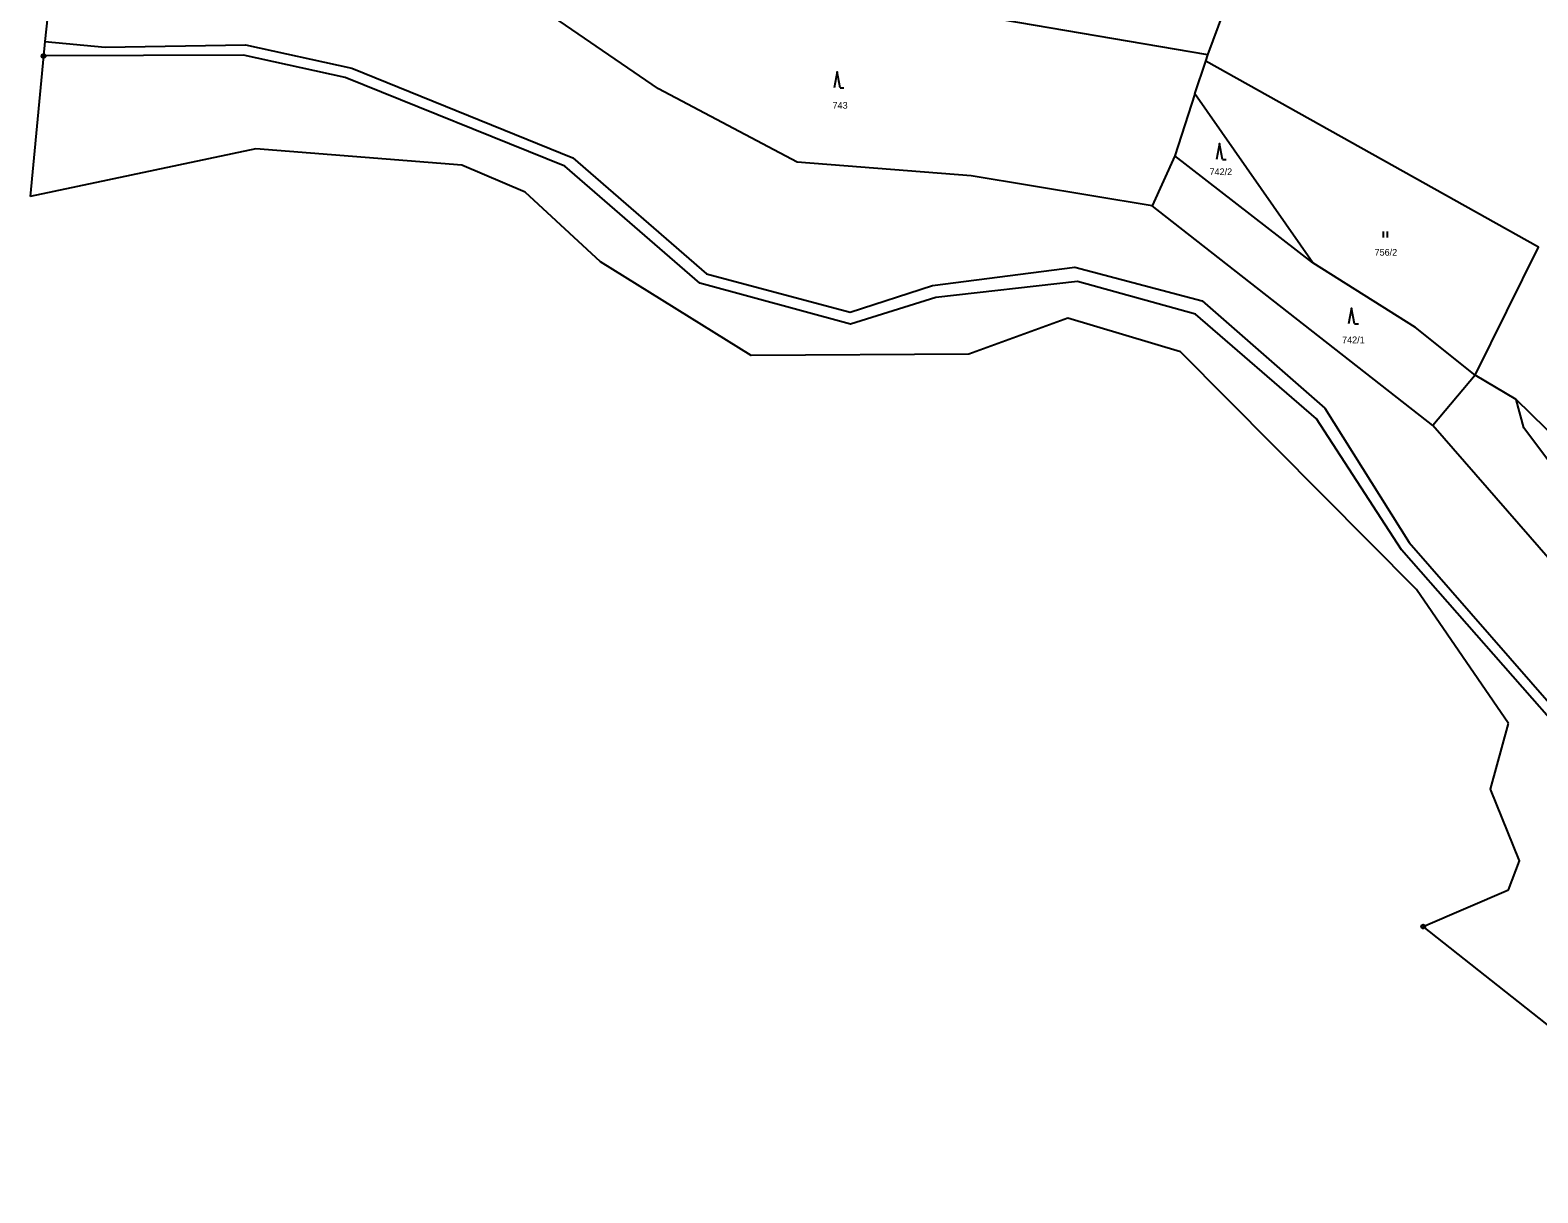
# Model space of a CAD drawing. Extents: x -687135 to -684370, y -1007309 to -1005782.
# Drawn here: x -686988.5 to -686608.2, y -1006718.8 to -1006425.4 of the extents above; entities that cross this region are included whole.
import ezdxf

# ---------------------------------------------------------------- set-up
doc = ezdxf.new("R2010")
doc.units = 0
doc.header["$LTSCALE"] = 0.68
for name, color, linetype, lineweight in [('1', 7, 'Continuous', 25), ('3', 7, 'Continuous', 25), ('8', 7, 'Continuous', 25)]:
    doc.layers.add(name, color=color, linetype=linetype, lineweight=lineweight)
doc.layers.add('2', color=7, linetype='Continuous')

msp = doc.modelspace()

# ---------------------------------------------------------------- linework, layer by layer
at = {"layer": '1'}
for p, q in [((-686984.16, -1006422.05), (-686984.76, -1006428.31)), ((-686984.76, -1006428.31), (-686985.11, -1006431.95)), ((-686985.11, -1006431.95), (-686988.5, -1006467.44)), ((-686699.82, -1006457.14), (-686705.53, -1006469.79)), ((-686624.03, -1006512.52), (-686634.73, -1006525.16))]:
    msp.add_line(p, q, dxfattribs=at)
for points in [[(-686691.44, -1006431.67), (-686681.78, -1006405.61), (-686676.16, -1006390.95), (-686669.85, -1006367.08)], [(-686694.78, -1006441.51), (-686691.95, -1006433.27), (-686691.44, -1006431.67), (-686787.33, -1006415.27)], [(-686705.53, -1006469.79), (-686751.17, -1006462.19), (-686795.04, -1006458.78), (-686830.03, -1006440.24), (-686862.81, -1006417.73)], [(-686984.76, -1006428.31), (-686969.57, -1006429.7), (-686934.19, -1006429.13), (-686907.35, -1006435.05), (-686851.6, -1006457.67), (-686817.92, -1006486.94), (-686781.69, -1006496.55), (-686760.9, -1006489.89), (-686724.99, -1006485.24), (-686692.9, -1006493.7), (-686661.95, -1006520.83), (-686640.73, -1006554.73), (-686599.57, -1006601.79), (-686576.51, -1006619.5), (-686545.07, -1006654.9), (-686452.7, -1006711.84), (-686422.4, -1006717.6), (-686386.45, -1006710.61), (-686333.13, -1006715.82), (-686262.62, -1006718.78), (-686241.47, -1006709.79), (-686203.86, -1006711.97)], [(-686600.54, -1006604.47), (-686642.63, -1006556.52), (-686664.07, -1006523.47), (-686694.59, -1006497.08), (-686724.36, -1006488.84), (-686760.06, -1006492.85), (-686781.59, -1006499.62), (-686819.61, -1006489.27), (-686853.61, -1006459.79), (-686909.04, -1006437.38), (-686934.72, -1006431.77), (-686985.11, -1006431.95)], [(-686624.03, -1006512.52), (-686608.08, -1006480.21), (-686691.95, -1006433.27)], [(-686664.97, -1006484.1), (-686694.78, -1006441.51), (-686699.82, -1006457.14)], [(-686879.64, -1006459.49), (-686931.58, -1006455.36), (-686988.5, -1006467.44)], [(-686624.03, -1006512.52), (-686639.11, -1006500.44), (-686664.97, -1006484.1), (-686699.82, -1006457.14)], [(-686615.67, -1006600.33), (-686638.85, -1006566.53), (-686698.37, -1006506.62), (-686726.75, -1006498.1), (-686751.73, -1006507.19), (-686806.61, -1006507.51), (-686844.67, -1006483.88), (-686863.64, -1006466.33), (-686879.64, -1006459.49)], [(-686378.58, -1006679.53), (-686376.49, -1006683.84), (-686426.43, -1006686.12), (-686455.76, -1006674.99), (-686575.36, -1006593.34), (-686634.73, -1006525.16), (-686705.53, -1006469.79)], [(-686560.65, -1006586.24), (-686578.06, -1006570.74), (-686611.76, -1006525.73), (-686613.68, -1006518.64), (-686624.03, -1006512.52)], [(-686560.65, -1006586.24), (-686553.58, -1006577.43), (-686613.68, -1006518.64)], [(-686615.61, -1006642.29), (-686612.84, -1006634.99), (-686620.21, -1006616.96), (-686615.67, -1006600.33)], [(-686604.28, -1006677.55), (-686637.15, -1006651.59), (-686615.61, -1006642.29)]]:
    msp.add_lwpolyline(points, dxfattribs=at)
at = {"layer": '3'}
for p, q in [((-686784.24, -1006439.96), (-686783.244, -1006439.96)), ((-686687.8, -1006458.03), (-686686.804, -1006458.03)), ((-686647.161, -1006477.74), (-686647.161, -1006476.24)), ((-686646.16, -1006477.74), (-686646.16, -1006476.24)), ((-686654.5, -1006499.56), (-686653.504, -1006499.56))]:
    msp.add_line(p, q, dxfattribs=at)
for points in [[(-686784.24, -1006439.96), (-686784.99, -1006435.96), (-686785.74, -1006439.96)], [(-686687.8, -1006458.03), (-686688.55, -1006454.03), (-686689.3, -1006458.03)], [(-686654.5, -1006499.56), (-686655.25, -1006495.56), (-686656, -1006499.56)]]:
    msp.add_lwpolyline(points, dxfattribs=at)
at = {"layer": '8'}
for centre, radius in [((-686985.11, -1006431.9499), 0.5), ((-686985.11, -1006431.9499), 0.0303), ((-686637.15, -1006651.5899), 0.5), ((-686637.15, -1006651.5899), 0.0303)]:
    msp.add_circle(centre, radius, dxfattribs=at)

# ---------------------------------------------------------------- texts
at = {"layer": '2'}
for s, p in [('743', (-686786.11, -1006445.25)), ('742/2', (-686691.03, -1006462.01)), ('756/2', (-686649.41, -1006482.33)), ('742/1', (-686657.6, -1006504.429))]:
    msp.add_text(s, height=1.7, dxfattribs=at).set_placement(p)

doc.saveas('drawing.dxf')
